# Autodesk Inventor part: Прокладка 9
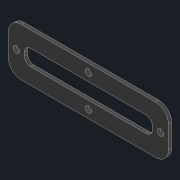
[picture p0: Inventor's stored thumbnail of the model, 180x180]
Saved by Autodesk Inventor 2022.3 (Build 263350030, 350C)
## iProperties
Created: 2022-08
Part Number: Прокладка 9
Material: Резина
Document SubType Name: Modeling
Designer: Карташов
Density: 0.93 g/cm^3
Appearance: Резина — черная
Author: Карташов
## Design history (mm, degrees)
sketch "Эскиз1"
  geometry: L1 (-0.001, -3.5)-(-0.001, 3.5) reference; L2 (-4.001, 7.5)-(-46.001, 7.5) reference; L3 (-50.001, 3.5)-(-50.001, -3.5) reference; L4 (-46.001, -7.5)-(-4.001, -7.5) reference; L5 (-43.001, -2.5)-(-7.001, -2.5) reference; L6 (-45.001, 0.5)-(-45.001, -0.5) reference; L7 (-7.001, 2.5)-(-43.001, 2.5) reference; L8 (-5.001, -0.5)-(-5.001, 0.5) reference; C1 r 1 at (-47.501, 0) reference; C2 r 1 at (-2.501, 0) reference; C3 r 1 at (-25.001, 5) reference; C4 r 1 at (-25.001, -5) reference; A1 r 4 centre (-4.001, 3.5) between (-0.001, 3.5) and (-4.001, 7.5) reference; A2 r 4 centre (-46.001, 3.5) between (-46.001, 7.5) and (-50.001, 3.5) reference; A3 r 4 centre (-46.001, -3.5) between (-50.001, -3.5) and (-46.001, -7.5) reference; A4 r 4 centre (-4.001, -3.5) between (-4.001, -7.5) and (-0.001, -3.5) reference; A5 r 2 centre (-7.001, -0.5) between (-7.001, -2.5) and (-5.001, -0.5) reference; A6 r 2 centre (-43.001, -0.5) between (-45.001, -0.5) and (-43.001, -2.5) reference; A7 r 2 centre (-43.001, 0.5) between (-43.001, 2.5) and (-45.001, 0.5) reference; A8 r 2 centre (-7.001, 0.5) between (-5.001, 0.5) and (-7.001, 2.5) reference; 1 further point
extrude "Выдавливание1" new body sketch "Эскиз1" distance "d0" = 1; taper "d1" = 0 deg
node "Твердое тело1"
node "Ссылка1"
